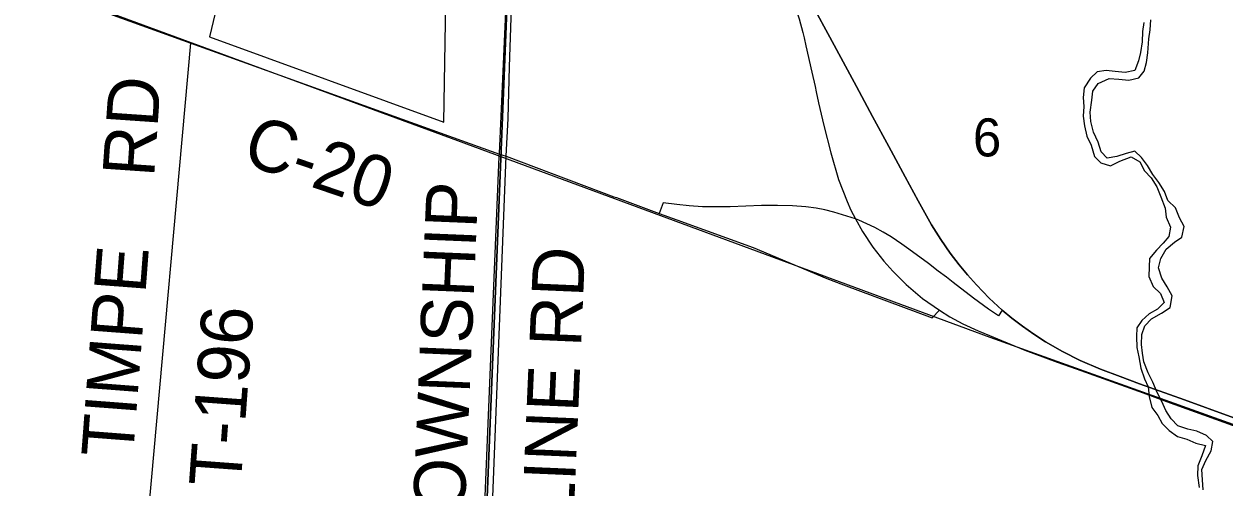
# Model space of a CAD drawing. Extents: x -8.5 to 18.7, y -20.3 to 7.
# Drawn here: x -1.362 to 1.276, y -0.499 to 0.52 of the extents above; entities that cross this region are included whole.
import ezdxf

# ---------------------------------------------------------------- set-up
doc = ezdxf.new("R2010")
doc.units = 0
for name, color, linetype in [('GM_X_City_Street', 7, 'Continuous'), ('GM_X_Corporation', 7, 'Continuous'), ('GM_X_County_Road', 7, 'Continuous'), ('GM_X_County_Road_Text', 7, 'Continuous'), ('GM_X_Interchange_Ramps', 7, 'Continuous'), ('GM_X_Minor_River', 7, 'Continuous'), ('GM_X_Rail_Line', 7, 'Continuous'), ('GM_X_Section', 7, 'Continuous'), ('GM_X_Section_Text', 7, 'Continuous'), ('GM_X_State_Route', 7, 'Continuous'), ('GM_X_Township', 7, 'Continuous'), ('GM_X_Township_Road', 7, 'Continuous'), ('GM_X_Township_Road_Text', 7, 'Continuous'), ('GM_X_US_Route', 7, 'Continuous')]:
    doc.layers.add(name, color=color, linetype=linetype)

msp = doc.modelspace()

# ---------------------------------------------------------------- linework, layer by layer
at = {"layer": 'GM_X_City_Street'}
msp.add_lwpolyline([(-1.4034, 1.2346), (-1.3485, 1.2346), (-1.3485, 1.2422), (-1.1685, 1.2422), (-1.1157, 1.0619), (-1.1524, 1.0625), (-1.1597, 0.644), (-1.0286, 0.5856), (-0.9421, 0.5435), (-0.955, 0.4916), (-0.4403, 0.3043), (-0.4273, 1.0509), (-0.4121, 1.0506), (-0.4121, 1.4832), (-0.2862, 1.481), (-0.2862, 1.5617), (-0.5367, 2.0462), (-0.8854, 2.05), (-0.5781, 2.1818), (-0.7808, 2.5298), (-0.8987, 2.7366)], dxfattribs=at)
at = {"layer": 'GM_X_Corporation'}
msp.add_lwpolyline([(-0.5243, -5.7448), (-0.5063, -4.8122), (-0.4738, -3.5008), (-0.4017, -1.8003), (-0.4011, -1.7879), (-0.3988, -1.7297), (-0.3182, 0.2282), (-0.3179, 0.2351), (-0.2815, 1.0573), (-1.2833, 1.077), (-1.3034, 1.0774), (-1.4067, 1.0795)], dxfattribs=at)
at = {"layer": 'GM_X_County_Road'}
msp.add_line((-0.3479, -0.9287), (-0.3034, 0.2289), dxfattribs=at)
for points in [[(-0.3034, 0.2289), (-0.2986, 0.3119), (-0.2955, 0.4254), (-0.2876, 0.6633), (-0.2788, 0.9108), (-0.274, 1.05), (-0.2721, 1.0547)], [(-1.3449, 0.6045), (-0.9961, 0.4778), (-0.3174, 0.2339), (-0.3034, 0.2289)], [(-0.3034, 0.2289), (-0.0663, 0.1399), (-0.0607, 0.1379)], [(-0.0607, 0.1379), (0.033, 0.1034), (0.072, 0.0892)], [(0.072, 0.0892), (0.2397, 0.0284), (0.4016, -0.0397)]]:
    msp.add_lwpolyline(points, dxfattribs=at)
at = {"layer": 'GM_X_Interchange_Ramps'}
for points in [[(0.6643, -0.0372), (0.6462, -0.0235), (0.6251, -0.0066), (0.5816, 0.0248), (0.5663, 0.0358), (0.5425, 0.0516), (0.5251, 0.0621), (0.5067, 0.0721), (0.4715, 0.0887), (0.4646, 0.0916), (0.4171, 0.1061), (0.3971, 0.1108), (0.3776, 0.1145), (0.3552, 0.1177), (0.326, 0.1201), (0.2932, 0.121), (0.2581, 0.1207), (0.1887, 0.118), (0.15, 0.1176), (0.128, 0.1179), (0.0989, 0.1197), (0.0717, 0.1225), (0.0418, 0.1265), (0.033, 0.1034)], [(0.4016, -0.0397), (0.4378, -0.0538), (0.6331, -0.1262), (0.6489, -0.1098)], [(0.7868, -0.1096), (0.7782, -0.1218), (0.7569, -0.1075), (0.7235, -0.0832), (0.6791, -0.0484), (0.6643, -0.0372)]]:
    msp.add_lwpolyline(points, dxfattribs=at)
at = {"layer": 'GM_X_Minor_River'}
for points in [[(1.2283, -0.5046), (1.2266, -0.4826), (1.2249, -0.4605), (1.2338, -0.4402), (1.2458, -0.4193), (1.2493, -0.3989), (1.2353, -0.3856), (1.2143, -0.3759), (1.1947, -0.3716), (1.1722, -0.3641), (1.1582, -0.3485), (1.1465, -0.33), (1.1372, -0.3108), (1.1271, -0.2907), (1.1179, -0.2677), (1.1071, -0.2477), (1.0979, -0.2231), (1.0946, -0.204), (1.0928, -0.185), (1.0934, -0.163), (1.1, -0.1442), (1.1148, -0.1287), (1.1364, -0.1163), (1.1557, -0.104), (1.1602, -0.0783), (1.1494, -0.0582), (1.1377, -0.0389), (1.13, -0.0167), (1.1351, 0.0044), (1.147, 0.0246), (1.1649, 0.0401), (1.1811, 0.051), (1.1863, 0.0744), (1.1762, 0.0937), (1.1677, 0.1152), (1.1507, 0.1316), (1.1429, 0.1516), (1.1305, 0.1716), (1.1174, 0.1887), (1.1058, 0.2088), (1.0926, 0.2266), (1.0778, 0.2399), (1.0587, 0.2351), (1.0388, 0.2281), (1.0175, 0.2249), (1.0042, 0.2389), (0.9972, 0.2603), (0.9872, 0.2819), (0.9817, 0.3056), (0.98, 0.3261), (0.9838, 0.3526), (0.9858, 0.3723), (0.9977, 0.3894), (1.0215, 0.4002), (1.0427, 0.3988), (1.0646, 0.3967), (1.0867, 0.4014), (1.0985, 0.4163), (1.1036, 0.4351), (1.1064, 0.4563), (1.1088, 0.4874), (1.1116, 0.507), (1.1129, 0.529)], [(1.0976, 0.5234), (1.0948, 0.5037), (1.0942, 0.4809), (1.0905, 0.4575), (1.0862, 0.4386), (1.078, 0.4176), (1.0567, 0.4129), (1.0348, 0.4157), (1.0151, 0.4178), (0.9953, 0.4146), (0.9805, 0.4005), (0.9671, 0.3796), (0.9642, 0.3585), (0.9659, 0.3387), (0.9646, 0.3174), (0.9678, 0.2961), (0.9725, 0.2732), (0.9818, 0.2532), (0.9895, 0.2287), (1.0035, 0.2146), (1.0246, 0.208), (1.0453, 0.218), (1.0699, 0.228), (1.0893, 0.2168), (1.0994, 0.1968), (1.1141, 0.1812), (1.1265, 0.1619), (1.135, 0.1396), (1.1449, 0.115), (1.1467, 0.0952), (1.1567, 0.073), (1.1531, 0.0525), (1.1406, 0.0377), (1.1257, 0.0222), (1.1101, 0.0044), (1.1096, -0.0146), (1.109, -0.0358), (1.1183, -0.0574), (1.1345, -0.073)], [(1.1345, -0.073), (1.1423, -0.093), (1.1275, -0.1077), (1.1098, -0.1179), (1.0935, -0.1326), (1.0824, -0.1483), (1.0819, -0.1672), (1.0828, -0.1916), (1.0868, -0.2122), (1.0914, -0.2374), (1.0991, -0.2604), (1.107, -0.278), (1.1095, -0.2994), (1.1156, -0.3238), (1.1288, -0.3417), (1.1382, -0.3586), (1.1537, -0.3742), (1.1715, -0.3876), (1.1926, -0.3935), (1.2121, -0.4024), (1.2332, -0.4076), (1.225, -0.4301), (1.2168, -0.4519), (1.2155, -0.4731), (1.2193, -0.4998)]]:
    msp.add_lwpolyline(points, dxfattribs=at)
at = {"layer": 'GM_X_Rail_Line'}
msp.add_lwpolyline([(-3.1051, 1.2532), (-2.4469, 1.0116), (-1.5221, 0.6739), (-0.4101, 0.2634), (0.7595, -0.1688), (1.8743, -0.5688), (3.1764, -1.0285), (4.3174, -1.4463), (6.1065, -2.1352), (6.899, -2.4421), (7.8038, -2.7637), (9.1245, -3.2289), (9.8265, -3.4832)], dxfattribs=at)
at = {"layer": 'GM_X_Section'}
for points in [[(-2.4613, 1.1112), (-2.2915, 1.1056), (-0.2815, 1.0613), (-0.3533, -0.74), (-0.3552, -0.7999), (-2.5517, -0.6423)], [(1.5424, 1.0872), (1.5257, -0.7471), (-0.3533, -0.74), (-0.2815, 1.0613)]]:
    msp.add_lwpolyline(points, close=True, dxfattribs=at)
at = {"layer": 'GM_X_State_Route'}
for points in [[(0.7868, -0.1096), (0.7579, -0.0835), (0.7299, -0.0542), (0.7102, -0.0322), (0.6918, -0.0098), (0.6721, 0.0159), (0.6517, 0.0457), (0.6316, 0.0782), (0.6023, 0.1309), (0.5737, 0.1835), (0.5377, 0.2503), (0.5018, 0.3168), (0.4662, 0.3827), (0.4371, 0.4367), (0.4079, 0.4911), (0.3724, 0.5566)], [(1.4188, -0.3912), (1.2872, -0.3434), (1.1869, -0.3071), (1.0882, -0.2714), (1.0456, -0.2557), (1.0027, -0.2393), (0.9582, -0.2202), (0.9189, -0.2007), (0.8818, -0.1794), (0.8559, -0.1625), (0.8312, -0.1451), (0.8077, -0.1273), (0.7868, -0.1096)]]:
    msp.add_lwpolyline(points, dxfattribs=at)
at = {"layer": 'GM_X_Township'}
msp.add_lwpolyline([(-0.5243, -5.7448), (-0.5063, -4.8122), (-0.4738, -3.5008), (-0.4017, -1.8003), (-0.4011, -1.7879), (-0.3988, -1.7297), (-0.3182, 0.2282), (-0.3179, 0.2351), (-0.2815, 1.0573), (-0.2719, 1.0573), (0.0749, 1.0561), (0.0888, 1.0559), (0.1031, 1.0557), (0.1184, 1.0556), (1.5463, 1.0836), (1.6213, 1.0837), (1.7309, 1.0848), (2.5365, 1.0994), (3.5551, 1.121), (3.6318, 1.1236), (5.043, 1.1473)], dxfattribs=at)
at = {"layer": 'GM_X_Township_Road'}
msp.add_line((-1.0954, -0.631), (-0.9961, 0.4778), dxfattribs=at)
at = {"layer": 'GM_X_US_Route'}
for points in [[(0.2788, 0.6791), (0.2912, 0.6552), (0.3087, 0.618), (0.3261, 0.5757), (0.3408, 0.5313), (0.3489, 0.5011), (0.3516, 0.4893)], [(0.3724, 0.5566), (0.4079, 0.4911), (0.4371, 0.4367), (0.4662, 0.3827), (0.5018, 0.3168), (0.5377, 0.2503), (0.5737, 0.1835), (0.6023, 0.1309), (0.6316, 0.0782), (0.6517, 0.0457), (0.6721, 0.0159), (0.6918, -0.0098), (0.7102, -0.0322), (0.7299, -0.0542), (0.7579, -0.0835), (0.7868, -0.1096)], [(0.3516, 0.4893), (0.3556, 0.4716), (0.3685, 0.4137), (0.3754, 0.3826), (0.3779, 0.3706)], [(0.3779, 0.3706), (0.3829, 0.3465), (0.3948, 0.2969), (0.4099, 0.2368), (0.4271, 0.1782), (0.4463, 0.1292), (0.4544, 0.1104), (0.4646, 0.0916), (0.4797, 0.0635), (0.5027, 0.0288), (0.5263, -0.0015), (0.5463, -0.024), (0.5756, -0.0533), (0.6113, -0.0836), (0.6489, -0.1098)], [(0.6489, -0.1098), (0.6718, -0.1243), (0.7, -0.1396), (0.7336, -0.1553), (0.7373, -0.1568)], [(0.7868, -0.1096), (0.8077, -0.1273), (0.8312, -0.1451), (0.8559, -0.1625), (0.8818, -0.1794), (0.9189, -0.2007), (0.9582, -0.2202), (1.0027, -0.2393), (1.0456, -0.2557), (1.0882, -0.2714), (1.1869, -0.3071), (1.2872, -0.3434), (1.4188, -0.3912)], [(0.7373, -0.1568), (0.8362, -0.1975), (0.9074, -0.2238), (0.9491, -0.239), (1.0961, -0.2918)], [(1.0961, -0.2918), (1.1476, -0.3103), (1.4179, -0.4084), (1.5316, -0.4485), (1.6229, -0.4819)]]:
    msp.add_lwpolyline(points, dxfattribs=at)

# ---------------------------------------------------------------- texts
at = {"layer": 'GM_X_County_Road_Text'}
for s, rotation, p in [('C-20', 341.1304, (-0.8874, 0.215)), ('TOWNSHIP', 87.6083, (-0.3982, -0.6479)), ('LINE RD', 87.541, (-0.155, -0.5715))]:
    msp.add_text(s, height=0.11364, rotation=rotation, dxfattribs=at).set_placement(p)
at = {"layer": 'GM_X_Section_Text'}
msp.add_text('6', height=0.0837, rotation=0, dxfattribs=at).set_placement((0.7223, 0.2286))
at = {"layer": 'GM_X_Township_Road_Text'}
for s, rotation, p in [('RD', 86.0551, (-1.0767, 0.1815)), ('TIMPE', 85.6371, (-1.1233, -0.4365)), ('T-196', 85.7948, (-0.8868, -0.5009))]:
    msp.add_text(s, height=0.11364, rotation=rotation, dxfattribs=at).set_placement(p)

doc.saveas('drawing.dxf')
